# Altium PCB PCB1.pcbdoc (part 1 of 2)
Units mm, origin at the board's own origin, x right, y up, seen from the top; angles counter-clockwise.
Board outline 376.79 x 262.39 mm, 2 copper layers (Top Layer, Bottom Layer), stack 1.58 mm thick; 505 components, 251 nets, 1356 pads, 0 vias.
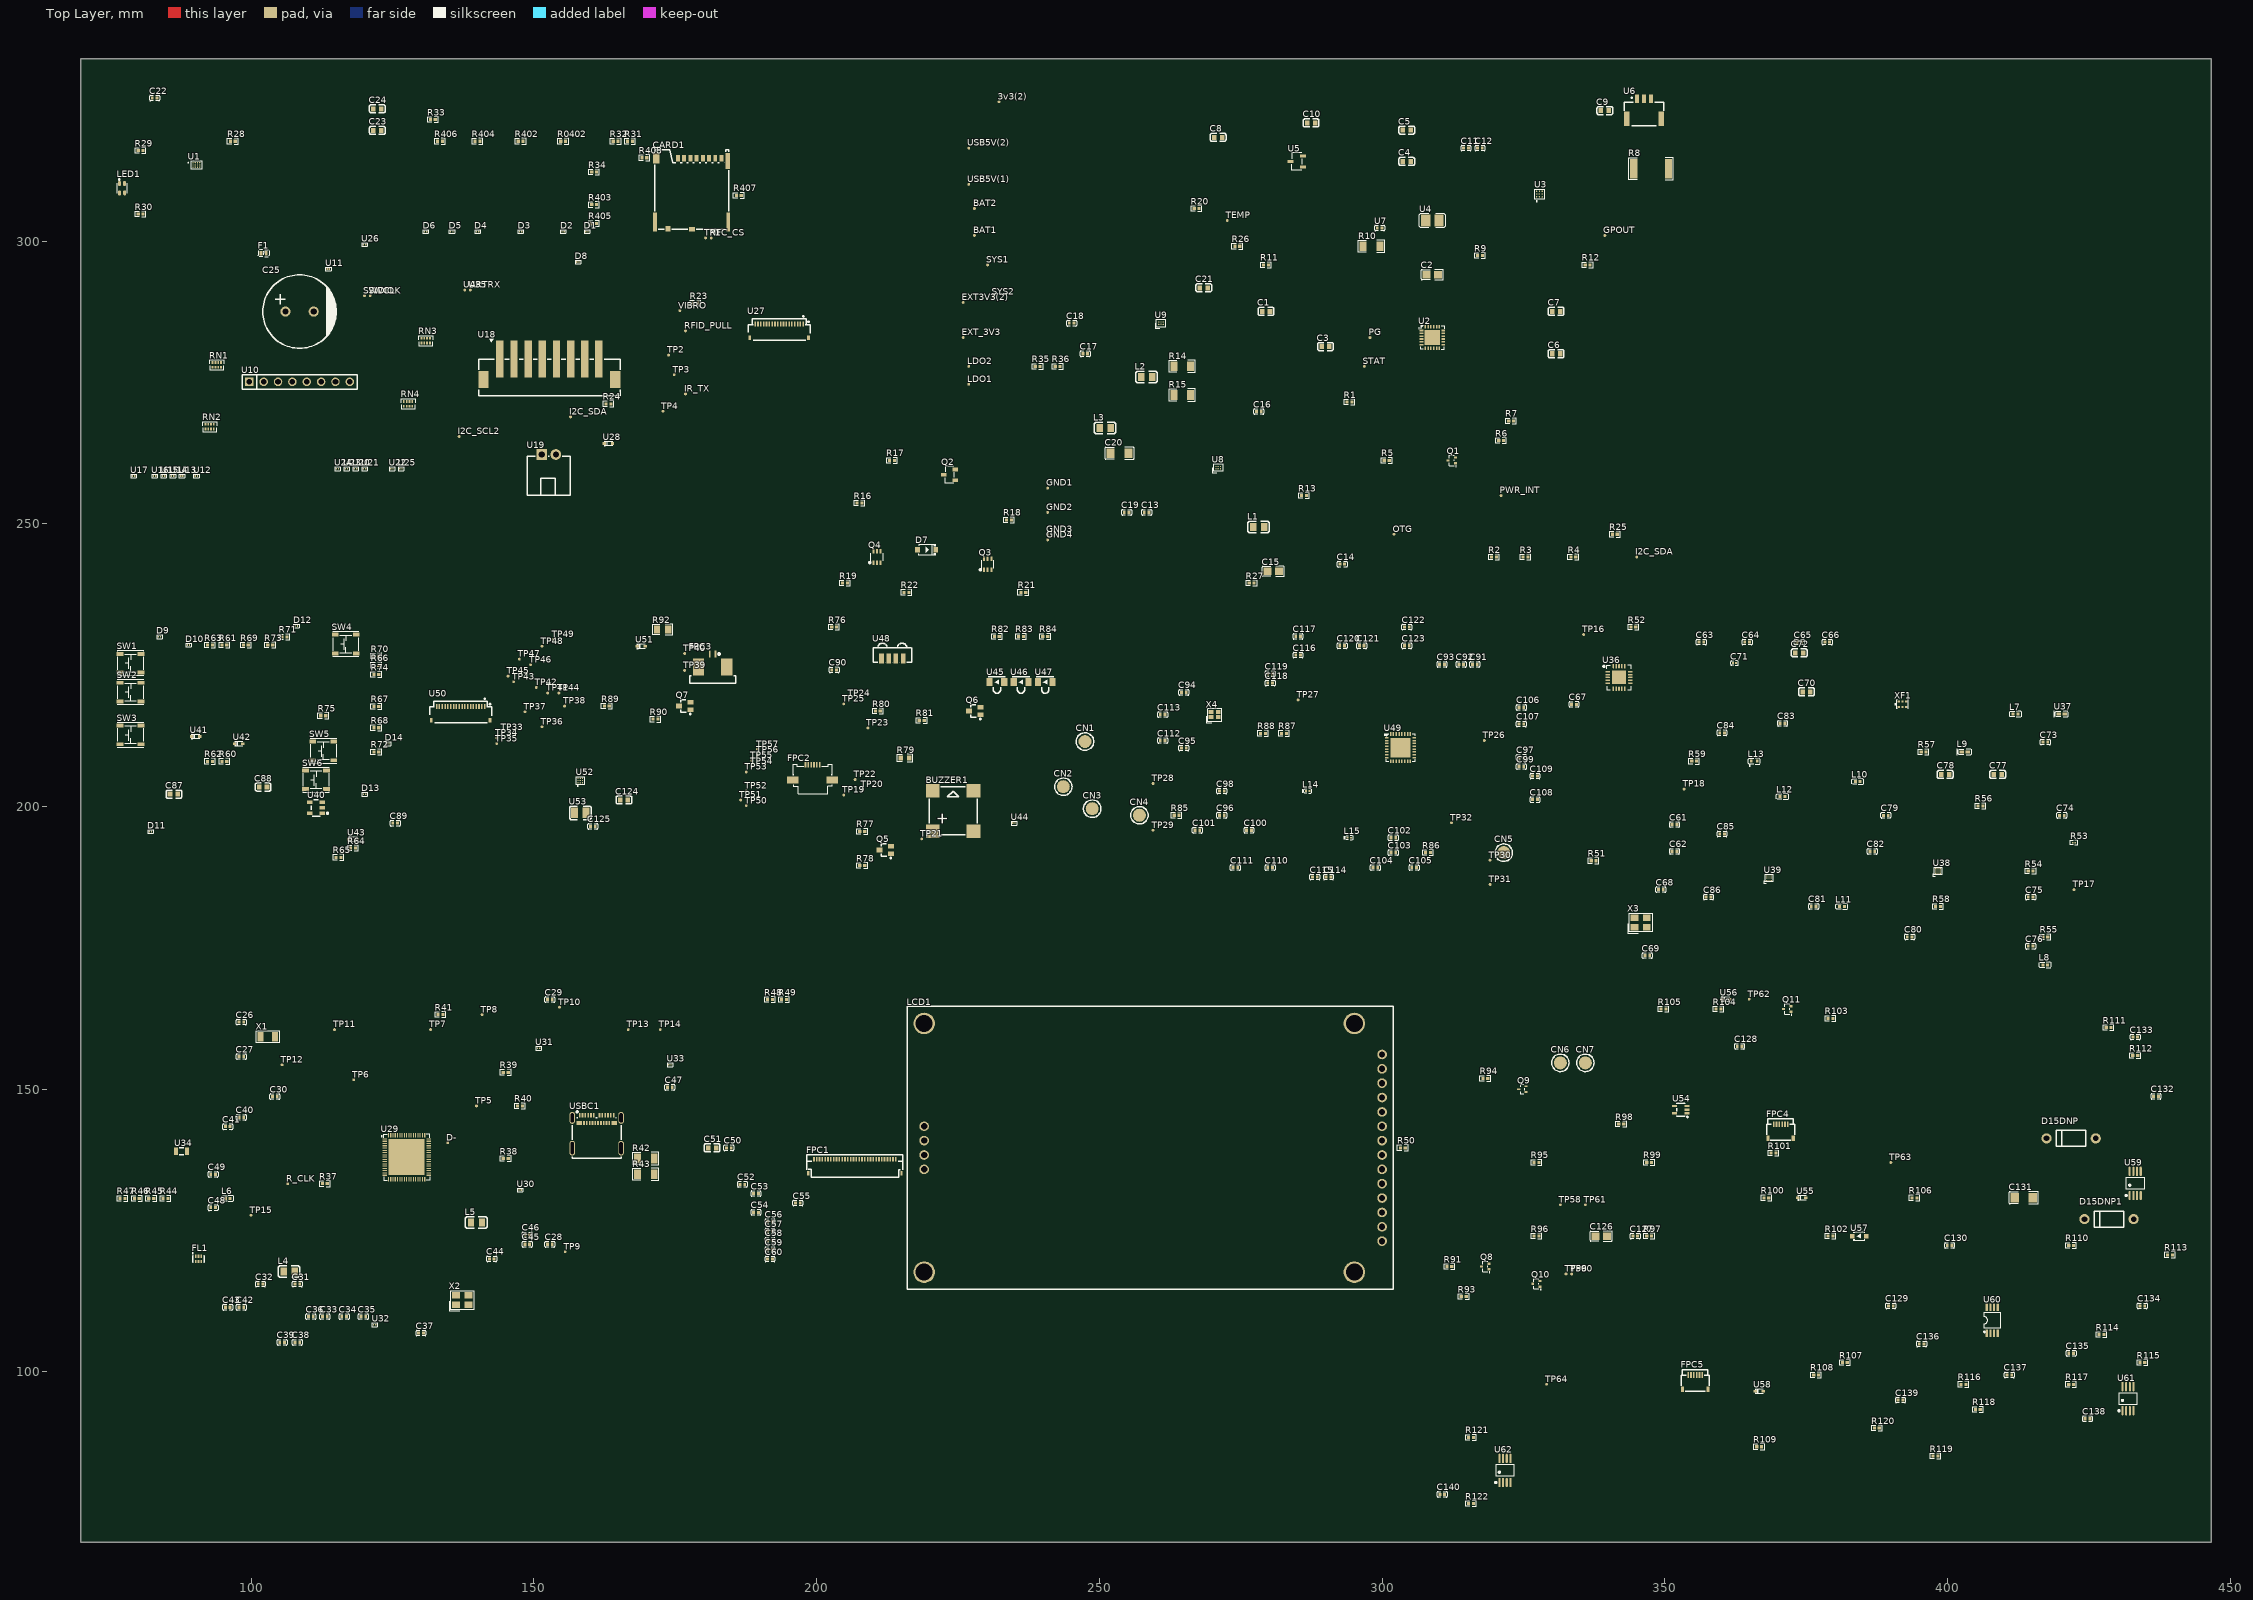
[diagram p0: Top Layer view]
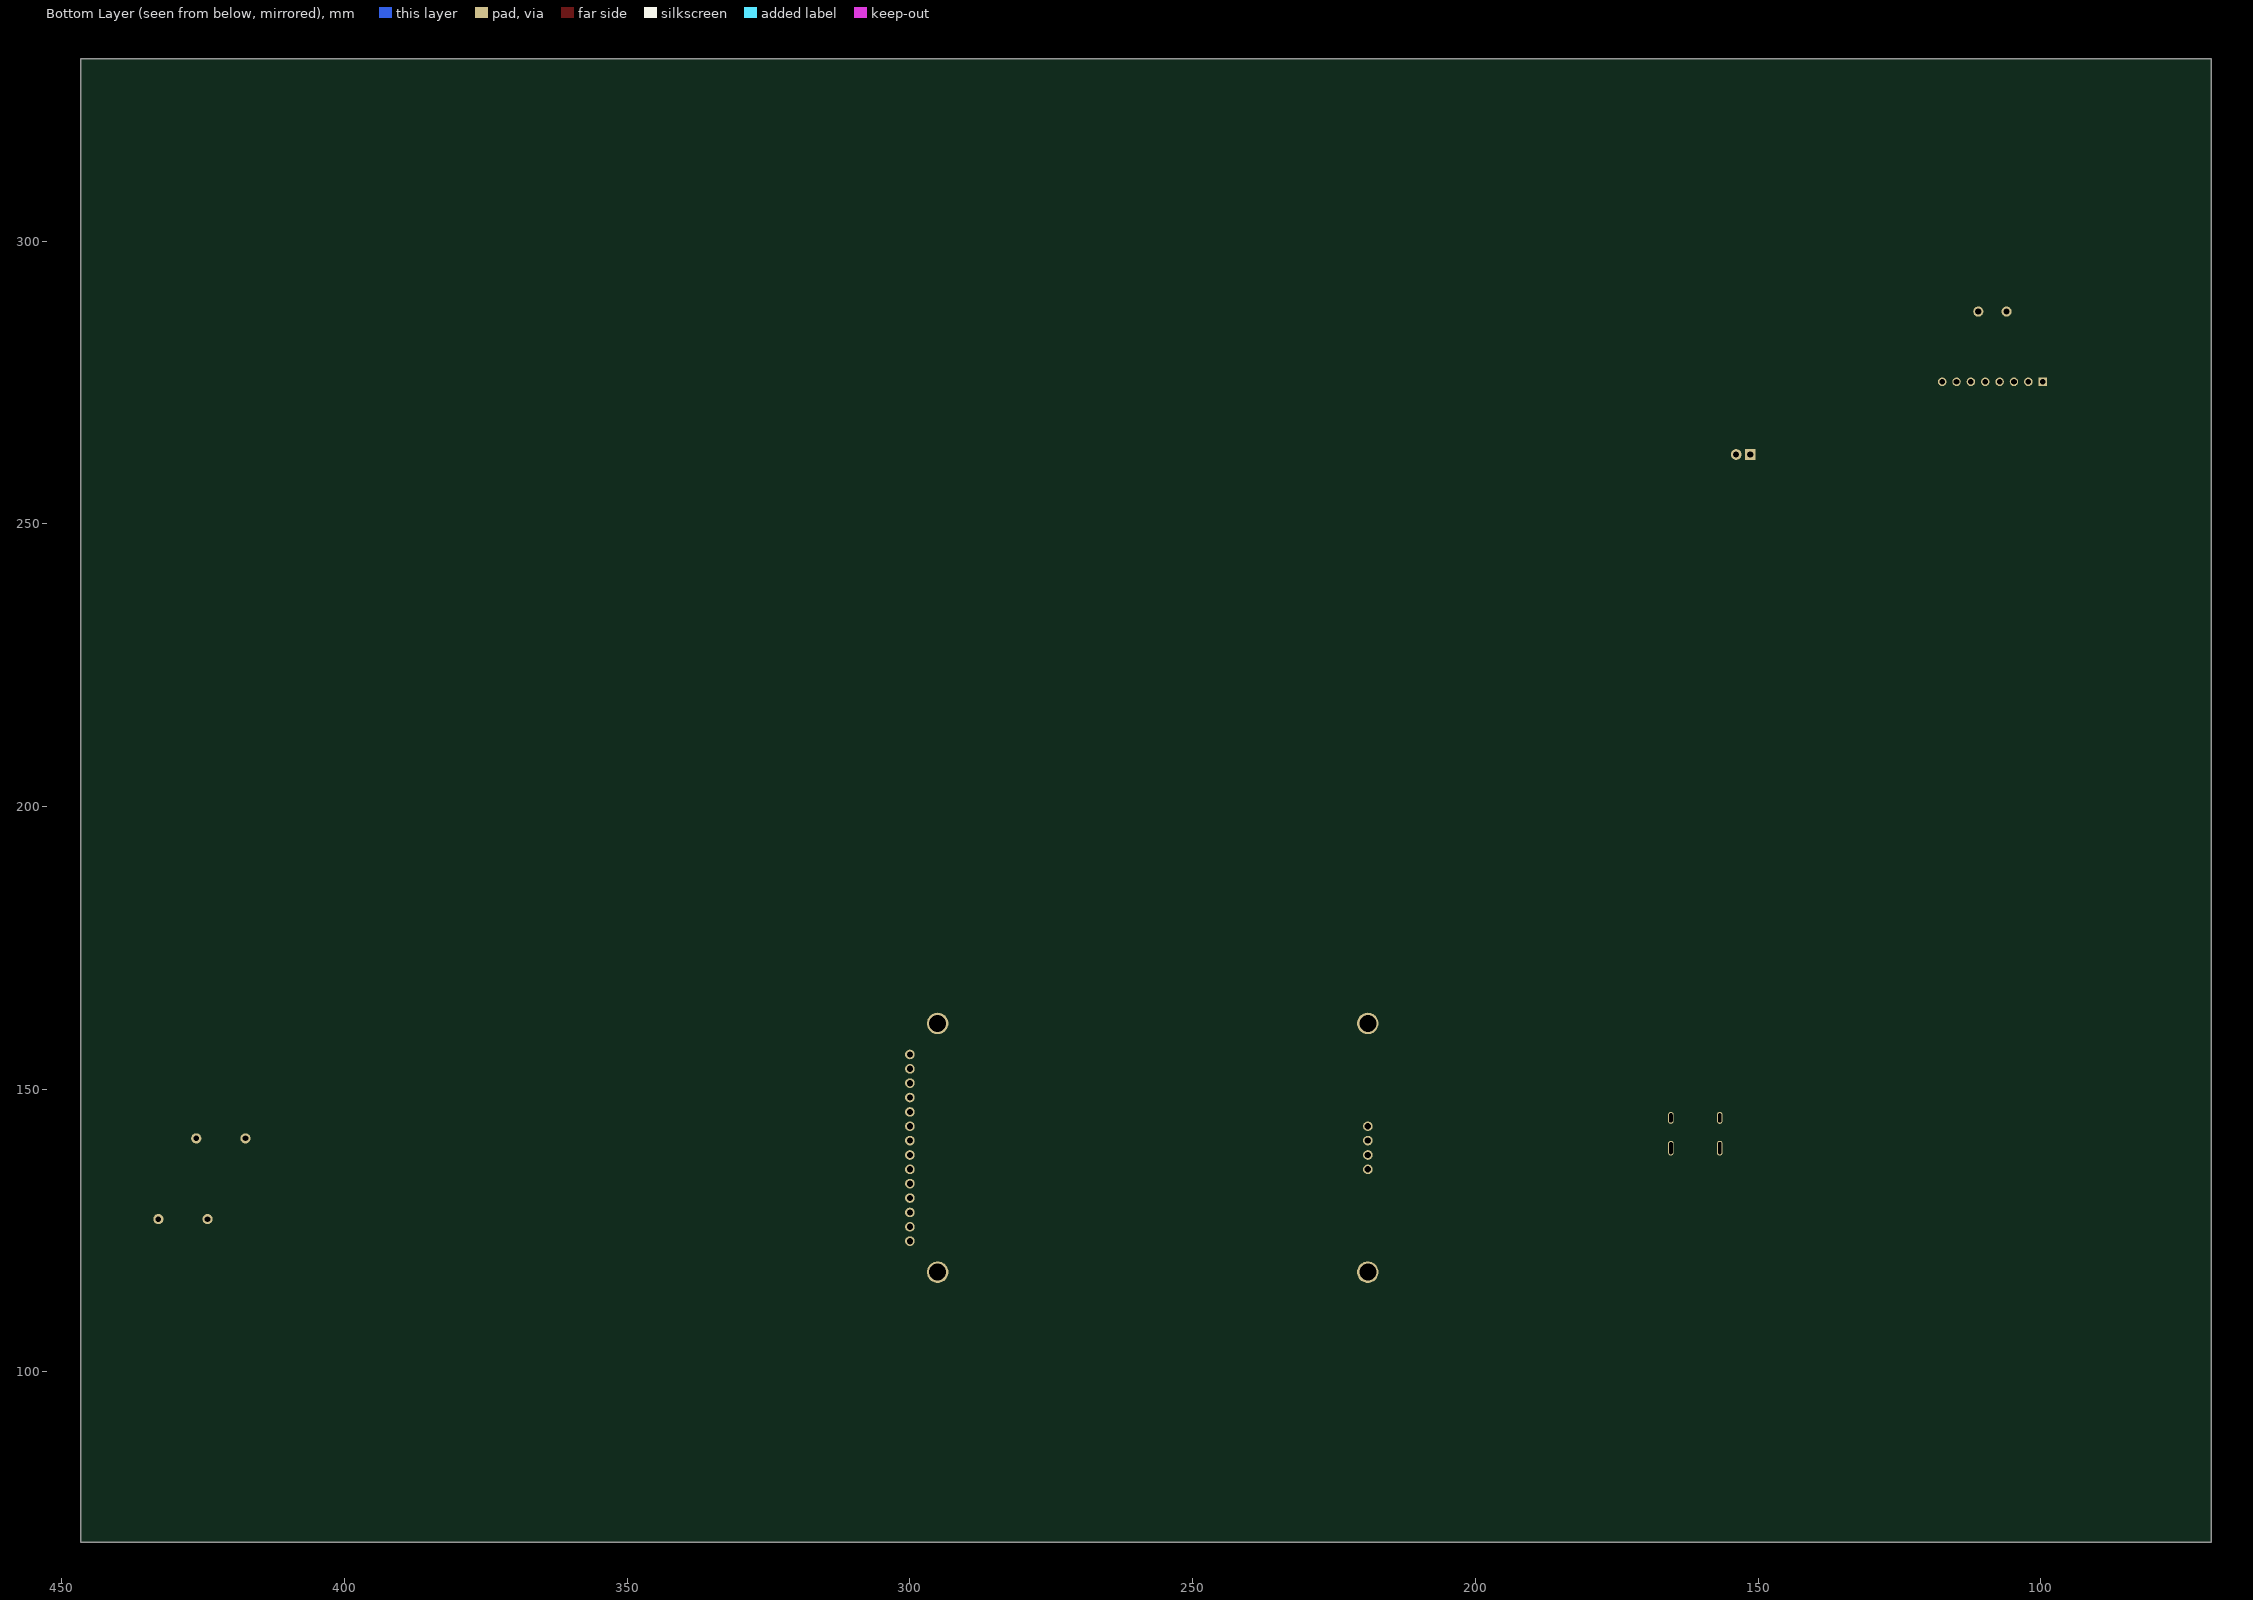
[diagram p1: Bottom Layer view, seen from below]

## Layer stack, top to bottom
Top Solder Mask Layer: solder mask 0.01, Dk 3.3
Top Layer: signal copper 0.035
Dielectric1: surface 1.51, FR4, Dk 4.5
Bottom Layer: signal copper 0.035
Bottom Solder Mask Layer: solder mask 0.01, Dk 3.3

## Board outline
446.638,69.85 69.85,69.85 69.85,332.242 446.638,332.242

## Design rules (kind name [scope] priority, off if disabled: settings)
BoardOutlineClearance copperThickness1oz [All] p0: genericclearance=0.254 ignorepadtopadclearanceinfootprint=FALSE except(0: Arc-SplitContinuation Track-SplitContinuation SMDPad-SplitContinuation THPad-SplitContinuation Via-SplitContinuation Fill-SplitContinuation Poly-SplitContinuation Region-SplitContinuation Text-SplitContinuation)
BoardOutlineClearance copperThickness2oz [All] p0: genericclearance=0.254 ignorepadtopadclearanceinfootprint=FALSE except(0: Arc-SplitContinuation Track-SplitContinuation SMDPad-SplitContinuation THPad-SplitContinuation Via-SplitContinuation Fill-SplitContinuation Poly-SplitContinuation Region-SplitContinuation Text-SplitContinuation)
BoardOutlineClearance otherClearance [All] p0: genericclearance=0.254 ignorepadtopadclearanceinfootprint=FALSE except(0: Arc-SplitContinuation Track-SplitContinuation SMDPad-SplitContinuation THPad-SplitContinuation Via-SplitContinuation Fill-SplitContinuation Poly-SplitContinuation Region-SplitContinuation Text-SplitContinuation)
Clearance copperThickness1oz [All] p1: gap=0.178 ignorepadtopadclearanceinfootprint=FALSE
Clearance copperThickness2oz [All] p1: gap=0.178 ignorepadtopadclearanceinfootprint=FALSE
Clearance otherClearance [All] p1: gap=0.178 ignorepadtopadclearanceinfootprint=FALSE
DiffPairsRouting differentialPair [All] p1: maxuncoupledlength=10 minlimit=6 maxlimit=Infinity mostfreqgap=6 toplayer_minwidth=5 toplayer_prefwidth=10 toplayer_maxwidth=100 bottomlayer_minwidth=5 bottomlayer_prefwidth=10 bottomlayer_maxwidth=100
PasteMaskExpansion pasteMaskExpansion [All] p1: expansion=0
PlaneConnect innerPlane [All] p1: planeconnectstyle=Relief reliefexpansion=0.508 reliefentries=4 reliefconductorwidth=0.254 reliefairgap=0.254
PolygonConnect copperRegion [All] p1: connectstyle=Relief reliefentries=4 reliefconductorwidth=10 polygonreliefangle="90 Angle" airgapwidth=10
RoutingVias viaSize [All] p1: viastyle="Through Hole" holewidth=12.0078 minholewidth=11.811 maxholewidth=248.0314 width=12.0078 minwidth=11.811 maxwidth=248.0314
SolderMaskExpansion solderMaskExpansion [IsVia] p1: useseparateexpansions=TRUE expansion=-1000 expansionbottom=-1000
SolderMaskExpansion solderMaskExpansion [All] p2: useseparateexpansions=TRUE expansion=2 expansionbottom=2
Width copperThickness1oz [All] p1: maxlimit=100 minlimit=5 preferedwidth=10
Width copperThickness2oz [All] p1: maxlimit=100 minlimit=8 preferedwidth=10

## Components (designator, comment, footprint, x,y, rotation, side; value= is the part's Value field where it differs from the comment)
3v3(2) "" Test-Point-0.5mm 232.234,324.662 r0 top
BAT1 "" Test-Point-0.5mm 227.906,300.996 r0 top
BAT2 "" Test-Point-0.5mm 227.906,305.769 r0 top
BUZZER1 "2.7kHz" BUZ-SMD_4P-L8.5-W8.5-P8.50-BR 224.132,199.223 r0 top
C1 "1uF" C0603 279.477,287.57 r0 top
C2 "47nF" C0805 308.886,294.061 r0 top
C3 "10uF" C0603 289.987,281.354 r0 top
C4 "10uF" C0603 304.369,314.095 r0 top
C5 "10uF" C0603 304.369,319.631 r0 top
C6 "10uF" C0603 330.784,280.084 r0 top
C7 "10uF" C0603 330.784,287.57 r0 top
C8 "1uF" C0603 271.003,318.361 r0 top
C9 "1uF" C0603 339.4,323.075 r0 top
C10 "1uF" C0603 287.447,320.901 r0 top
C11 "470nF" C0402#1 314.84,316.448 r0 top
C12 "2.2uF" C0402#1 317.31,316.448 r0 top
C13 "2.2uF" C0402#1 258.352,252.019 r0 top
C14 "10uF" C0402#1 292.954,242.859 r0 top
C15 "4.7uF" C0805 280.747,241.589 r0 top
C16 "2.2uF" C0402#1 278.207,269.864 r0 top
C17 "2.2uF" C0402#1 247.497,280.084 r0 top
C18 "10uF" C0402#1 245.097,285.481 r0 top
C19 "10uF" C0402#1 254.829,252.019 r0 top
C20 "4.7uF" C1206 253.559,262.482 r0 top
C21 "2.2uF" C0603 268.463,291.744 r0 top
C22 "1uF" C0402#1 82.896,325.316 r0 top
C23 "10uF" C0603 122.292,319.579 r0 top
C24 "10uF" C0603 122.292,323.403 r0 top
C25 "DNP tatalum" CAP-TH_BD13.0-P5.00-D0.6-FD 108.536,287.541 r0 top
C26 "18pF" C0402#1 98.238,161.864 r0 top
C27 "18pF" C0402#1 98.238,155.776 r0 top
C28 "DNP" C0402#2 152.813,122.575 r0 top
C29 "DNP" C0402#2 152.813,165.841 r0 top
C30 "100nF" C0402#2 104.178,148.692 r0 top
C31 "0.8pf" C0402#2 108.148,115.542 r0 top
C32 "0.3PF" C0402#2 101.638,115.542 r0 top
C33 "100nF" C0402#2 113.018,109.789 r0 top
C34 "100nF" C0402#2 116.418,109.789 r0 top
C35 "100nF" C0402#2 119.818,109.789 r0 top
C36 "4.7uF" C0402#2 110.548,109.789 r0 top
C37 "100nF" C0402#2 130.01,106.876 r0 top
C38 "1nF" C0402#2 108.148,105.224 r0 top
C39 "10nF" C0402#2 105.448,105.224 r0 top
C40 "1nF" C0402#2 98.238,145.022 r0 top
C41 "100nF" C0402#2 95.838,143.37 r0 top
C42 "100nF" C0402#2 98.238,111.441 r0 top
C43 "100pF" C0402#2 95.838,111.441 r0 top
C44 "4.7uF" C0402#2 142.53,119.979 r0 top
C45 "4.7uF" C0402#2 148.812,122.575 r0 top
C46 "100nF" C0402#2 148.812,124.227 r0 top
C47 "100nF" C0402#2 174.036,150.344 r0 top
C48 "1.5pF" C0402#2 93.242,129.042 r0 top
C49 "100nF" C0402#2 93.242,134.939 r0 top
C50 "100nF" C0402#2 184.47,139.638 r0 top
C51 "10uF" C0603 181.503,139.638 r0 top
C52 "DNP" C0402#2 186.87,133.183 r0 top
C53 "DNP" C0402#2 189.27,131.531 r0 top
C54 "2.2uF" C0402#2 189.27,128.228 r0 top
C55 "DNP" C0402#2 196.681,129.88 r0 top
C56 "DNP" C0402#2 191.74,126.576 r0 top
C57 "DNP" C0402#2 191.74,124.925 r0 top
C58 "DNP" C0402#2 191.74,123.273 r0 top
C59 "DNP" C0402#2 191.74,121.621 r0 top
C60 "2.2uF" C0402#2 191.74,119.969 r0 top
C61 "100nF" C0402#2 351.716,196.799 r0 top
C62 "100nF" C0402#2 351.716,192.062 r0 top
C63 "100nF" C0402#2 356.457,229.085 r0 top
C64 "100nF" C0402#2 364.553,229.085 r0 top
C65 "100nF" C0402#2 373.792,229.085 r0 top
C66 "100nF" C0402#2 378.732,229.085 r0 top
C67 "100nF" C0402#2 333.94,218.076 r0 top
C68 "9pF" C0402#2 349.316,185.302 r0 top
C69 "9pF" C0402#2 346.916,173.643 r0 top
C70 "100pF" C0603 375.062,220.288 r0 top
C71 "0.6pF" C0201 362.34,225.368 r0 top
C72 "100pF" C0603 373.792,227.172 r0 top
C73 "DNP" C0402#2 417.307,211.39 r0 top
C74 "1.2pF" C0402#2 420.229,198.451 r0 top
C75 "DNP" C0402#2 414.711,183.976 r0 top
C76 "DNP" C0402#2 414.711,175.295 r0 top
C77 "10pF" C0603 408.883,205.681 r0 top
C78 "10pF" C0603 399.591,205.681 r0 top
C79 "22pF" C0402#2 389.115,198.451 r0 top
C80 "8.2pF" C0402#2 393.31,176.946 r0 top
C81 "DNP" C0402#2 376.332,182.325 r0 top
C82 "10nF" C0402#2 386.715,192.062 r0 top
C83 "DNP" C0402#2 370.825,214.694 r0 top
C84 "DNP" C0402#2 360.127,213.042 r0 top
C85 "100nF" C0402#2 360.127,195.147 r0 top
C86 "10nF" C0402#2 357.727,183.976 r0 top
C87 "10uF" C0603 86.32,202.18 r0 top
C88 "10uF" C0603 102.079,203.45 r0 top
C89 "100nF" C0402#2 125.453,197.049 r0 top
C90 "100nF" C0402#2 203.085,224.178 r0 top
C91 "DNP" C0402#2 316.396,225.128 r0 top
C92 "DNP" C0402#2 313.996,225.128 r0 top
C93 "DNP" C0402#2 310.596,225.128 r0 top
C94 "6pF" C0402#2 264.936,220.173 r0 top
C95 "6pF" C0402#2 264.936,210.353 r0 top
C96 "100pF" C0402#2 271.655,198.456 r0 top
C97 "10pF" C0402#2 324.64,208.701 r0 top
C98 "DNP" C0402#2 271.655,202.746 r0 top
C99 "100pF" C0402#2 324.64,207.049 r0 top
C100 "680pF" C0402#2 276.455,195.805 r0 top
C101 "62pF" C0402#2 267.336,195.805 r0 top
C102 "100pF" C0402#2 301.985,194.479 r0 top
C103 "DNP" C0402#2 301.985,191.84 r0 top
C104 "680pF" C0402#2 298.805,189.189 r0 top
C105 "62pF" C0402#2 305.655,189.189 r0 top
C106 "10pF" C0402#2 324.64,217.521 r0 top
C107 "100pF" C0402#2 324.64,214.599 r0 top
C108 "1uF" C0402#2 327.04,201.203 r0 top
C109 "10nF" C0402#2 327.04,205.398 r0 top
C110 "10nF" C0402#2 280.196,189.189 r0 top
C111 "2.2uF" C0402#2 274.055,189.189 r0 top
C112 "10nF" C0402#2 261.196,211.679 r0 top
C113 "2.2uF" C0402#2 261.196,216.251 r0 top
C114 "10nF" C0402#2 290.522,187.538 r0 top
C115 "2.2uF" C0402#2 288.122,187.538 r0 top
C116 "10nF" C0402#2 285.137,226.779 r0 top
C117 "2.2uF" C0402#2 285.137,230.083 r0 top
C118 "10nF" C0402#2 280.196,221.824 r0 top
C119 "2.2uF" C0402#2 280.196,223.476 r0 top
C120 "10nF" C0402#2 292.922,228.431 r0 top
C121 "2.2uF" C0402#2 296.405,228.431 r0 top
C122 "10nF" C0402#2 304.385,231.734 r0 top
C123 "2.2uF" C0402#2 304.385,228.431 r0 top
C124 "22uF" C0603 165.917,201.155 r0 top
C125 "10uF" C0402#2 160.409,196.483 r0 top
C126 "3.3nF" C0805 338.739,124.016 r0 top
C127 "DNP" C0402#2 344.77,124.016 r0 top
C128 "100nF" C0402#2 363.225,157.585 r0 top
C129 "10nF" C0402#2 389.985,111.679 r0 top
C130 "1nF" C0402#2 400.367,122.366 r0 top
C131 "220nF" C1206 413.483,130.798 r0 top
C132 "100nF" C0402#2 436.873,148.735 r0 top
C133 "dnp" C0402#2 433.203,159.237 r0 top
C134 "4.7nF" C0402#2 434.473,111.679 r0 top
C135 "100pF" C0402#2 421.873,103.297 r0 top
C136 "100nF" C0402#2 395.426,104.948 r0 top
C137 "4.7nF" C0402#2 410.943,99.462 r0 top
C138 "100pF" C0402#2 424.763,91.715 r0 top
C139 "100pF" C0402#2 391.685,95.016 r0 top
C140 "1uF" C0402#2 310.635,78.349 r0 top
CARD1 "5033981892" TF-SMD_503398-1892 177.877,308.398 r0 top
CN1 "YTC1P-3515-M20" CONN-SMD_YTC1P-3515-M20 247.46,211.491 r0 top
CN2 "YTC1P-3515-M20" CONN-SMD_YTC1P-3515-M20 243.615,203.503 r0 top
CN3 "YTC1P-3515-M20" CONN-SMD_YTC1P-3515-M20 248.73,199.61 r0 top
CN4 "YTC1P-3515-M20" CONN-SMD_YTC1P-3515-M20 257.074,198.456 r0 top
CN5 "YTC1P-3515-M20" CONN-SMD_YTC1P-3515-M20 321.518,191.84 r0 top
CN6 "YTC1P-3515-M20" CONN-SMD_YTC1P-3515-M20 331.527,154.664 r0 top
CN7 "YTC1P-3515-M20" CONN-SMD_YTC1P-3515-M20 335.949,154.664 r0 top
D1 "ESD241B1W0201E6327XTSA1" WLL-2-3_L0.6-W0.3-P0.36-BI 159.364,301.684 r0 top
D2 "ESD241B1W0201E6327XTSA1" WLL-2-3_L0.6-W0.3-P0.36-BI 155.161,301.684 r0 top
D3 "ESD241B1W0201E6327XTSA1" WLL-2-3_L0.6-W0.3-P0.36-BI 147.643,301.684 r0 top
D4 "ESD241B1W0201E6327XTSA1" WLL-2-3_L0.6-W0.3-P0.36-BI 140.023,301.684 r0 top
D5 "ESD241B1W0201E6327XTSA1" WLL-2-3_L0.6-W0.3-P0.36-BI 135.453,301.684 r0 top
D6 "ESD241B1W0201E6327XTSA1" WLL-2-3_L0.6-W0.3-P0.36-BI 130.841,301.684 r0 top
D7 "DNP" SOD-123_L2.7-W1.6-LS3.7-FD 219.446,245.399 r0 top
D8 "ESD241B1W0201E6327XTSA1" WLL-2-3_L0.6-W0.3-P0.36-BI 157.763,296.311 r0 top
D9 "ESD241B1W0201E6327XTSA1" WLL-2-3_L0.6-W0.3-P0.36-BI 83.753,230.006 r0 top
D10 "ESD241B1W0201E6327XTSA1" WLL-2-3_L0.6-W0.3-P0.36-BI 88.888,228.55 r0 top
D11 "ESD241B1W0201E6327XTSA1" WLL-2-3_L0.6-W0.3-P0.36-BI 82.151,195.592 r0 top
D12 "ESD241B1W0201E6327XTSA1" WLL-2-3_L0.6-W0.3-P0.36-BI 107.961,231.929 r0 top
D13 "ESD241B1W0201E6327XTSA1" WLL-2-3_L0.6-W0.3-P0.36-BI 120.04,202.18 r0 top
D14 "ESD241B1W0201E6327XTSA1" WLL-2-3_L0.6-W0.3-P0.36-BI 124.183,211.105 r0 top
D15DNP "" DO-41_BD2.4-L4.7-P8.70-D0.9-RD 421.873,141.302 r0 top
D15DNP1 "" DO-41_BD2.4-L4.7-P8.70-D0.9-RD 428.573,127.023 r0 top
D- "" Test-Point-0.5mm 134.75,140.532 r0 top
EXT3V3(2) "" Test-Point-0.5mm 225.906,289.157 r0 top
EXT_3V3 "" Test-Point-0.5mm 225.906,282.941 r0 top
F1 "ERBRD2R00X" F0402 102.186,297.867 r0 top
FL1 "LFL182G45TC1A108" FILTET-SMD_0603-6P-L1.6-W0.8-P0.50_LFL182G45TC1A108 90.665,119.979 r0 top
FPC1 "FH34SRJ-30S-0.5SH(50)" FFC-SMD_30P-P0.50_FH34SRJ-30S-0.5SH 206.758,136.386 r0 top
FPC2 "5051100697" FPC-SMD_6P-P0.50_5051100697 199.275,206.043 r0 top
FPC3 "1.0K-LS-2PWB-TW" FPC-SMD_1.0K-LS-2PWB-TW 181.588,225.801 r0 top
FPC4 "FH34SRJ-6S-0.5SH(50)" FFC-SMD_6P-P0.50_FH34SRJ-6S-0.5SH 370.505,142.572 r0 top
FPC5 "FH34SRJ-6S-0.5SH(50)" FFC-SMD_6P-P0.50_FH34SRJ-6S-0.5SH 355.392,98.192 r0 top
GND1 "" Test-Point-0.5mm 240.856,256.319 r0 top
GND2 "" Test-Point-0.5mm 240.856,252.019 r0 top
GND3 "" Test-Point-0.5mm 240.856,248.154 r0 top
GND4 "" Test-Point-0.5mm 240.856,247.154 r0 top
GPOUT "" Test-Point-0.5mm 339.4,300.996 r0 top
I2C_SCL2 "" Test-Point-0.5mm 136.753,265.437 r0 top
I2C_SDA "" Test-Point-0.5mm 345.048,244.129 r0 top
I2C_SDA "" Test-Point-0.5mm 156.462,268.906 r0 top
IR_TX "" Test-Point-0.5mm 176.797,272.966 r0 top
L1 "470nH" L0805 278.207,249.424 r0 top
L2 "470nH" L0805 258.352,275.96 r0 top
L3 "470nH" L0805 251.019,266.943 r0 top
L4 "2.7nh" L0805 106.718,117.761 r0 top
L5 "10uH" L0805 139.83,126.446 r0 top
L6 "3nH" L0402 95.838,130.702 r0 top
L7 "3.3nH" L0402 412.045,216.354 r0 top
L8 "56nH" L0402 417.307,172.001 r0 top
L9 "27nH" L0402-RD 403.08,209.668 r0 top
L10 "22nH" L0402 384.119,204.411 r0 top
L11 "2.7nH" L0402 381.328,182.325 r0 top
L12 "DNP" L0402 370.825,201.76 r0 top
L13 "2.2nH" IND-SMD_L1.0-W0.5_LQG15HN1N6B02D 365.823,208.018 r0 top
L14 "270nH" L0201-RD 286.852,202.746 r0 top
L15 "270nH" L0201-RD 294.192,194.479 r0 top
LCD1 "HS12864G18B" COMM-TH_HS12864G18B 259.51,139.638 r0 top
LDO1 "" Test-Point-0.5mm 226.906,274.69 r0 top
LDO2 "" Test-Point-0.5mm 226.906,277.853 r0 top
LED1 "LTST-C19HE1WT" LED-ARRAY-SMD_4P-L1.6-W1.6-TL-CW 77.152,309.359 r0 top
NFC_CS "" Test-Point-0.5mm 181.338,300.553 r0 top
OTG "" Test-Point-0.5mm 302.102,248.154 r0 top
PG "" Test-Point-0.5mm 297.862,282.941 r0 top
PWR_INT "" Test-Point-0.5mm 321.051,254.994 r0 top
Q1 "DMN313DLT-7" SOT-523-3_L1.6-W0.8-P1.00-LS1.6-BR 312.33,261.212 r0 top
Q2 "DMP1045U-7" SOT-23-3_L2.9-W1.3-P1.90-LS2.4-BR 223.496,258.672 r0 top
Q3 "MMDT2907A-7-F" SOT-363_L2.0-W1.3-P0.65-LS2.1-BL 230.234,242.859 r0 top
Q4 "MMDT2907A-7-F" SOT-363_L2.0-W1.3-P0.65-LS2.1-BL 210.662,244.129 r0 top
Q5 "DMN2058UW-7" SOT-323-3_L2.2-W1.3-P1.30-LS2.1-BR 212.096,192.3 r0 top
Q6 "DMN2058UW-7" SOT-323-3_L2.2-W1.3-P1.30-LS2.1-BR 227.942,216.888 r0 top
Q7 "DMN2058UW-7" SOT-323-3_L2.2-W1.3-P1.30-LS2.1-BR 176.636,217.767 r0 top
Q8 "CJE3134K" SOT-523-3_L1.6-W0.8-P1.00-LS1.6-BR 318.257,118.646 r0 top
Q9 "CJE3139K" SC-75-3_L1.6-W0.8-P1.00-LS1.7-BR 324.813,150.005 r0 top
Q10 "CJE3134K" SOT-523-3_L1.6-W0.8-P1.00-LS1.6-BR 327.296,115.577 r0 top
Q11 "DMN5L06TK-7" SOT-523-3_L1.6-W0.8-P1.00-LS1.6-BR 371.661,164.187 r0 top
R1 "470Ω" R0402 294.224,271.514 r0 top
R2 "4.7kΩ" R0402 319.781,244.129 r0 top
R3 "1.5kΩ" R0402 325.362,244.129 r0 top
R4 "1.5kΩ" R0402 333.822,244.129 r0 top
R5 "10K" R0402 300.832,261.212 r0 top
R6 "100Ω" R0402 321.051,264.725 r0 top
R7 "10K" R0402 322.821,268.213 r0 top
R8 "10mΩ" R2512 347.588,312.825 r0 top
R9 "10K" R0402 317.31,297.441 r0 top
R10 "5.23ohm" R1206 298.132,299.09 r0 top
R11 "30.1kΩ" R0402 279.477,295.791 r0 top
R12 "10K" R0402 336.363,295.791 r0 top
R13 "10K" R0402 286.177,254.994 r0 top
R14 "1R5" R1206 264.653,277.853 r0 top
R15 "1R5" R1206 264.653,272.784 r0 top
R16 "nettie" R0402 207.564,253.67 r0 top
R17 "nettie" R0402 213.334,261.212 r0 top
R18 "100kΩ" R0402 234.004,250.694 r0 top
R19 "100kΩ" R0402 205.023,239.535 r0 top
R20 "DNP" R0402 267.193,305.769 r0 top
R21 "10K" R0402 236.545,237.885 r0 top
R22 "10K" R0402 215.875,237.885 r0 top
R23 "51Ω" R0402 178.568,289.026 r0 top
R24 "1kΩ" R0402 163.175,271.231 r0 top
R25 "nettie" R0402 341.17,248.154 r0 top
R26 "nettie" R0402 274.396,299.09 r0 top
R27 "nettie" R0402 276.937,239.535 r0 top
R28 "0Ω" R0402 96.729,317.667 r0 top
R29 "0Ω" R0402 80.426,316.018 r0 top
R30 "0Ω" R0402 80.426,304.79 r0 top
R31 "47kΩ" R0402 166.986,317.667 r0 top
R32 "47kΩ" R0402 164.445,317.667 r0 top
R33 "0Ω" R0402 132.111,321.491 r0 top
R34 "51Ω" R0402 160.634,312.208 r0 top
R35 "3.3Ω" R0402 239.086,277.853 r0 top
R36 "3.3Ω" R0402 242.627,277.853 r0 top
R37 "51Ω" R0402 113.018,133.288 r0 top
R38 "22Ω" R0402 145.001,137.75 r0 top
R39 "DNP" R0402 145.001,152.995 r0 top
R40 "22Ω" R0402 147.542,147.042 r0 top
R41 "51Ω" R0402 133.48,163.19 r0 top
R42 "5.1K" R1206 169.796,137.75 r0 top
R43 "5.1K" R1206 169.796,134.939 r0 top
R44 "0Ω" R0402 84.843,130.702 r0 top
R45 "DNP" R0402 82.302,130.702 r0 top
R46 "DNP" R0402 79.761,130.702 r0 top
R47 "DNP" R0402 77.22,130.702 r0 top
R48 "DNP" R0402 191.74,165.842 r0 top
R49 "DNP" R0402 194.211,165.842 r0 top
R50 "0Ω" R0402 303.665,139.638 r0 top
R51 "330Ω" R0402 337.411,190.411 r0 top
R52 "56kΩ" R0402 344.446,231.736 r0 top
R53 "0Ω" R0201 422.377,193.605 r0 top
R54 "0Ω" R0402 414.711,188.598 r0 top
R55 "0Ω" R0402 417.307,176.946 r0 top
R56 "0Ω" R0402 405.845,200.101 r0 top
R57 "0Ω" R0402 395.78,209.668 r0 top
R58 "0Ω" R0402 398.321,182.325 r0 top
R59 "0Ω" R0402 355.187,208.018 r0 top
R60 "100kΩ" R0402 95.235,208 r0 top
R61 "DNP" R0402 95.235,228.55 r0 top
R62 "100kΩ" R0402 92.694,208 r0 top
R63 "10K" R0402 92.694,228.55 r0 top
R64 "510Ω" R0402 117.973,192.666 r0 top
R65 "10K" R0402 115.433,191.016 r0 top
R66 "330Ω" R0402 122.111,224.977 r0 top
R67 "330Ω" R0402 122.111,217.702 r0 top
R68 "330Ω" R0402 122.111,213.935 r0 top
R69 "10K" R0402 99.042,228.55 r0 top
R70 "330Ω" R0402 122.111,226.627 r0 top
R71 "10K" R0402 105.89,230.006 r0 top
R72 "330Ω" R0402 122.111,209.649 r0 top
R73 "10K" R0402 103.349,228.55 r0 top
R74 "330Ω" R0402 122.111,223.328 r0 top
R75 "10K" R0402 112.732,216.052 r0 top
R76 "10Ω" R0402 203.085,231.736 r0 top
R77 "150Ω" R0402 208.055,195.602 r0 top
R78 "10K" R0402 208.055,189.552 r0 top
R79 "22Ω" R0603 215.6,208.583 r0 top
R80 "150Ω" R0402 210.826,216.888 r0 top
R81 "10K" R0402 218.582,215.238 r0 top
R82 "39Ω" R0402 231.872,230.086 r0 top
R83 "39Ω" R0402 236.148,230.086 r0 top
R84 "39Ω" R0402 240.423,230.086 r0 top
R85 "0Ω" R0402 263.666,198.456 r0 top
R86 "0Ω" R0402 308.126,191.84 r0 top
R87 "DNP" R0402 282.666,212.949 r0 top
R88 "DNP" R0402 278.926,212.949 r0 top
R89 "150Ω" R0402 162.879,217.767 r0 top
R90 "10K" R0402 171.486,215.442 r0 top
R91 "51Ω" R0402 311.905,118.646 r0 top
R92 "22Ω" R0805 172.756,231.317 r0 top
R93 "10K" R0402 314.446,113.33 r0 top
R94 "510Ω" R0402 318.257,151.918 r0 top
R95 "4.7Ω" R0402 327.296,137.05 r0 top
R96 "4.7Ω" R0402 327.296,124.016 r0 top
R97 "DNP" R0402 347.24,124.016 r0 top
R98 "330kΩ" R0402 342.299,143.842 r0 top
R99 "DNP" R0402 347.24,137.05 r0 top
R100 "0Ω" R0402 367.965,130.798 r0 top
R101 "10K" R0402 369.235,138.7 r0 top
R102 "330kΩ" R0402 379.314,124.016 r0 top
R103 "330Ω" R0402 379.314,162.537 r0 top
R104 "220Ω" R0402 359.489,164.187 r0 top
R105 "220Ω" R0402 349.781,164.187 r0 top
R106 "5.1kΩ" R0402 394.156,130.798 r0 top
R107 "47kΩ" R0402 381.854,101.646 r0 top
R108 "51Ω" R0402 376.773,99.462 r0 top
R109 "10K" R0402 366.695,86.765 r0 top
R110 "1MΩ" R0402 421.873,122.366 r0 top
R111 "" R0402 428.503,160.887 r0 top
R112 "4.7kΩ" R0402 433.203,155.934 r0 top
R113 "" R0402 439.344,120.716 r0 top
R114 "" R0402 427.233,106.599 r0 top
R115 "10K" R0402 434.473,101.646 r0 top
R116 "1kΩ" R0402 402.837,97.812 r0 top
R117 "1kΩ" R0402 421.873,97.812 r0 top
R118 "10K" R0402 405.378,93.365 r0 top
R119 "33kΩ" R0402 397.896,85.115 r0 top
R120 "20kΩ" R0402 387.515,90.064 r0 top
R121 "33kΩ" R0402 315.716,88.415 r0 top
R122 "33kΩ" R0402 315.716,76.699 r0 top
R0402 "DNP" R0402 155.161,317.667 r0 top
R402 "DNP" R0402 147.643,317.667 r0 top
R403 "51Ω" R0402 160.634,306.439 r0 top
R404 "DNP" R0402 140.023,317.667 r0 top
R405 "51Ω" R0402 160.634,303.14 r0 top
R406 "47kΩ" R0402 133.381,317.667 r0 top
R407 "150Ω" R0402 186.228,308.089 r0 top
R408 "150Ω" R0402 169.527,314.748 r0 top
R_CLK "" Test-Point-0.5mm 106.448,133.288 r0 top
RFID_PULL "" Test-Point-0.5mm 176.797,284.127 r0 top
RN1 "51Ω" RES-ARRAY-SMD_0402-8P-L2.0-W1.0-BL 93.903,278.118 r0 top
RN2 "51Ω" RES-ARRAY-SMD_0402-8P-L2.0-W1.0-BL 92.633,267.172 r0 top
RN3 "51Ω" RES-ARRAY-SMD_0402-8P-L2.0-W1.0-BL 130.841,282.393 r0 top
RN4 "51Ω" RES-ARRAY-SMD_0402-8P-L2.0-W1.0-BL 127.732,271.231 r0 top
STAT "" Test-Point-0.5mm 296.862,277.853 r0 top
SW1 "SKRMAAE010" SW-SMD_4P-L4.5-W4.5-P3.30-S3.75 78.65,225.357 r0 top
SW2 "SKRMAAE010" SW-SMD_4P-L4.5-W4.5-P3.30-S3.75 78.65,220.242 r0 top
SW3 "SKRMAAE010" SW-SMD_4P-L4.5-W4.5-P3.30-S3.75 78.65,212.665 r0 top
SW4 "SKRMAAE010" SW-SMD_4P-L4.5-W4.5-P3.30-S3.75 116.703,228.736 r0 top
SW5 "SKRMAAE010" SW-SMD_4P-L4.5-W4.5-P3.30-S3.75 112.732,209.835 r0 top
SW6 "SKRMAAE010" SW-SMD_4P-L4.5-W4.5-P3.30-S3.75 111.462,204.72 r0 top
SWCLK "" Test-Point-0.5mm 121.022,290.351 r0 top
SWDIO "" Test-Point-0.5mm 120.022,290.351 r0 top
SYS1 "" Test-Point-0.5mm 230.234,295.791 r0 top
SYS2 "SYS1" Test-Point-0.5mm 231.234,290.157 r0 top
TEMP "" Test-Point-0.5mm 272.626,303.647 r0 top
TP1 "RFID_IN" Test-Point-0.5mm 180.338,300.553 r0 top
TP2 "RFID_OUT" Test-Point-0.5mm 173.797,279.853 r0 top
TP3 "SPEAKER" Test-Point-0.5mm 174.797,276.383 r0 top
TP4 "RFID_CARRIED" Test-Point-0.5mm 172.797,269.906 r0 top
TP5 "D+" Test-Point-0.5mm 139.83,147.042 r0 top
TP6 "D_MI" Test-Point-0.5mm 118.118,151.67 r0 top
TP7 "R_MI" Test-Point-0.5mm 131.71,160.539 r0 top
TP8 "R_MO" Test-Point-0.5mm 140.83,163.19 r0 top
TP9 "D_MO" Test-Point-0.5mm 155.513,121.249 r0 top
TP10 "D_SCK" Test-Point-0.5mm 154.513,164.515 r0 top
TP11 "BOOT" Test-Point-0.5mm 114.718,160.539 r0 top
TP12 "NRST" Test-Point-0.5mm 105.448,154.319 r0 top
TP13 "VBUS2" Test-Point-0.5mm 166.659,160.539 r0 top
TP14 "VBUS1" Test-Point-0.5mm 172.336,160.539 r0 top
TP15 "BLE" Test-Point-0.5mm 99.938,127.716 r0 top
TP16 "CC_PWD" Test-Point-0.5mm 335.64,230.411 r0 top
TP17 "Balun" Test-Point-0.5mm 422.377,185.302 r0 top
TP18 "SUB1Ghz" Test-Point-0.5mm 353.416,203.077 r0 top
TP19 "SYS" Test-Point-0.5mm 204.785,202.033 r0 top
TP20 "SPEAKER" Test-Point-0.5mm 208.055,203.033 r0 top
TP21 "SPEAKER 1" Test-Point-0.5mm 218.582,194.277 r0 top
TP22 "iBTN" Test-Point-0.5mm 206.785,204.773 r0 top
TP23 "IR_TX" Test-Point-0.5mm 209.055,213.913 r0 top
TP24 "IR_RX" Test-Point-0.5mm 205.785,219.158 r0 top
TP25 "GND" Test-Point-0.5mm 204.785,218.158 r0 top
TP26 "CP1" Test-Point-0.5mm 318.096,211.679 r0 top
TP27 "CP2" Test-Point-0.5mm 285.137,218.847 r0 top
TP28 "AN2" Test-Point-0.5mm 259.496,204.072 r0 top
TP29 "ANT1" Test-Point-0.5mm 259.496,195.805 r0 top
TP30 "AN1" Test-Point-0.5mm 319.096,190.515 r0 top
TP31 "ANT2" Test-Point-0.5mm 319.096,186.212 r0 top
TP32 "CP3" Test-Point-0.5mm 312.296,197.131 r0 top
TP33 "NFC_CS" Test-Point-0.5mm 144.407,213.118 r0 top
TP34 "GND2" Test-Point-0.5mm 143.407,212.118 r0 top
TP35 "GND3" Test-Point-0.5mm 143.407,211.118 r0 top
TP36 "SPI_R_SCK" Test-Point-0.5mm 151.407,214.118 r0 top
TP37 "SPI_R_MISO" Test-Point-0.5mm 148.407,216.767 r0 top
TP38 "VIBRO" Test-Point-0.5mm 155.407,217.767 r0 top
TP39 "VIBRO2" Test-Point-0.5mm 176.636,224.071 r0 top
TP40 "VIBRO3" Test-Point-0.5mm 176.636,227.071 r0 top
TP41 "RFID_PULL" Test-Point-0.5mm 152.407,220.071 r0 top
TP42 "RFID_OUT" Test-Point-0.5mm 150.407,221.071 r0 top
TP43 "SPI_R_MOSI" Test-Point-0.5mm 146.407,222.071 r0 top
TP44 "" Test-Point-0.5mm 154.407,220.071 r0 top
TP45 "iBTN" Test-Point-0.5mm 145.407,223.071 r0 top
TP46 "SPEAKER" Test-Point-0.5mm 149.407,225.071 r0 top
TP47 "IR_TX" Test-Point-0.5mm 147.407,226.071 r0 top
TP48 "IR_RX" Test-Point-0.5mm 151.407,228.339 r0 top
TP49 "RFID_CARRIED" Test-Point-0.5mm 153.407,229.574 r0 top
TP50 "GND_2" Test-Point-0.5mm 187.54,200.155 r0 top
TP51 "GND_1" Test-Point-0.5mm 186.54,201.155 r0 top
TP52 "3V3_2" Test-Point-0.5mm 187.54,202.743 r0 top
TP53 "3V3_1" Test-Point-0.5mm 187.54,206.118 r0 top
TP54 "5V_2" Test-Point-0.5mm 188.54,207.118 r0 top
TP55 "5V_1" Test-Point-0.5mm 188.54,208.118 r0 top
TP56 "SYS2" Test-Point-0.5mm 189.54,209.118 r0 top
TP57 "SYS1" Test-Point-0.5mm 189.54,210.118 r0 top
TP58 "AR1" Test-Point-0.5mm 331.527,129.563 r0 top
TP59 "ANT3" Test-Point-0.5mm 332.527,117.322 r0 top
TP60 "ANT4" Test-Point-0.5mm 333.527,117.322 r0 top
TP61 "AR2" Test-Point-0.5mm 335.949,129.563 r0 top
TP62 "NFC_IRQ" Test-Point-0.5mm 364.925,165.932 r0 top
TP63 "DET" Test-Point-0.5mm 389.985,137.05 r0 top
TP64 "1.65V" Test-Point-0.5mm 329.105,97.812 r0 top
U1 "LP5562TMX/NOPB" DSBGA-12_L1.7-W1.3-R3-C4-P0.40-TL 90.278,313.478 r0 top
U2 "BQ25896RTWR" QFN-24_L4.0-W4.0-P0.50-TL-EP2.7 308.886,282.941 r0 top
U3 "BQ27220YZFR" DSBGA-9_L1.7-W1.6-R3-C3-P0.50-BL 327.825,308.33 r0 top
U4 "1uH" L1008 308.886,303.647 r0 top
U5 "XC6206P332MR" SOT-23-3_L3.0-W1.7-P0.95-LS2.9-BR 284.907,314.095 r0 top
U6 "1.25-3PWTDK" CONN-SMD_3P-P1.25_SHOU_1.25-3PWTDK 346.318,323.392 r0 top
U7 "4.7uF" C0402#1 299.562,302.321 r0 top
U8 "LM3281YFQR" DSBGA-6_L1.4-W1.1-R3-C2-P0.40-BL 271.003,259.942 r0 top
U9 "LM3281YFQR" DSBGA-6_L1.4-W1.1-R3-C2-P0.40-BL 260.894,285.481 r0 top
U10 "2.54-1*8" HDR-TH_8P-P2.54-V-M 108.536,275.113 r0 top
U11 "ESD230B1W0201E6327XTSA1" WLL-2-1_L0.6-W0.3-BI 113.616,295.049 r0 top
U12 "ESD230B1W0201E6327XTSA1" WLL-2-1_L0.6-W0.3-BI 90.278,258.465 r0 top
U13 "ESD230B1W0201E6327XTSA1" WLL-2-1_L0.6-W0.3-BI 87.701,258.465 r0 top
U14 "ESD230B1W0201E6327XTSA1" WLL-2-1_L0.6-W0.3-BI 86.099,258.465 r0 top
U15 "ESD230B1W0201E6327XTSA1" WLL-2-1_L0.6-W0.3-BI 84.498,258.465 r0 top
U16 "ESD230B1W0201E6327XTSA1" WLL-2-1_L0.6-W0.3-BI 82.896,258.465 r0 top
U17 "ESD230B1W0201E6327XTSA1" WLL-2-1_L0.6-W0.3-BI 79.156,258.465 r0 top
U18 "2.54mm-8P LT" CONN-SMD_8P-P2.50_SHOUHAN_2.54MM-8PLT 152.723,277.313 r0 top
U19 "2.54mm-2P WZ" CONN-TH_2P-P2.50_HX-2.54MM-2P-WZ-1 152.621,262.267 r0 top
U20 "ESD230B1W0201E6327XTSA1" WLL-2-1_L0.6-W0.3-BI 118.421,259.727 r0 top
U21 "ESD230B1W0201E6327XTSA1" WLL-2-1_L0.6-W0.3-BI 120.022,259.727 r0 top
U22 "ESD230B1W0201E6327XTSA1" WLL-2-1_L0.6-W0.3-BI 124.86,259.727 r0 top
U23 "ESD230B1W0201E6327XTSA1" WLL-2-1_L0.6-W0.3-BI 116.819,259.727 r0 top
U24 "ESD230B1W0201E6327XTSA1" WLL-2-1_L0.6-W0.3-BI 115.218,259.727 r0 top
U25 "ESD230B1W0201E6327XTSA1" WLL-2-1_L0.6-W0.3-BI 126.462,259.727 r0 top
U26 "ESD230B1W0201E6327XTSA1" WLL-2-1_L0.6-W0.3-BI 120.022,299.423 r0 top
U27 "FH34SRJ-18S-0.5SH(50)" FFC-SMD_18P-P0.50_FH34SRJ-18S-0.5SH 193.375,284.127 r0 top
U28 "1N4148X-TP" SOD-523F_L1.2-W0.8-LS1.7-RD 163.175,264.202 r0 top
U29 "STM32WB55RGV6TR" QFN-68_L8.0-W8.0-P0.40-TL-EP6.4 127.47,137.992 r0 top
U30 "ESD230B1W0201E6327XTSA1" WLL-2-1_L0.6-W0.3-BI 147.542,132.158 r0 top
U31 "ESD230B1W0201E6327XTSA1" WLL-2-1_L0.6-W0.3-BI 150.813,157.233 r0 top
U32 "ESD230B1W0201E6327XTSA1" WLL-2-1_L0.6-W0.3-BI 121.819,108.333 r0 top
U33 "ESD230B1W0201E6327XTSA1" WLL-2-1_L0.6-W0.3-BI 174.036,154.319 r0 top
U34 "1001312" ANT-SMD_L2.0-W1.2-BI 87.664,139.02 r0 top
U35 "UART_TX" Test-Point-0.5mm 138.753,291.351 r0 top
U36 "CC1101RGPR" QFN-20_L4.0-W4.0-P0.5-TL-EP 341.906,222.828 r0 top
U37 "6.8nH" L0402-RD 420.229,216.354 r0 top
U38 "BGS13S4N9E6327XTSA1" TSNP-9_L1.1-W1.1-P0.40-BL 398.321,188.598 r0 top
U39 "BGS13S4N9E6327XTSA1" TSNP-9_L1.1-W1.1-P0.40-BL 368.441,187.328 r0 top
U40 "NC7SZ32M5X" SOT-23-5_L2.9-W1.6-P0.95-LS2.8-BR 111.462,199.775 r0 top
U41 "1N4148X-TP" SOD-523F_L1.2-W0.8-LS1.7-RD 90.158,212.375 r0 top
U42 "1N4148X-TP" SOD-523F_L1.2-W0.8-LS1.7-RD 97.772,211.105 r0 top
U43 "1N4148X-TP" SOD-523F_L1.2-W0.8-LS1.7-RD 117.973,194.226 r0 top
U44 "ESD230B1W0201E6327XTSA1" WLL-2-1_L0.6-W0.3-BI 234.878,197.058 r0 top
U45 "VSMY14940" LED-SMD_VSMY14940 231.872,222.005 r0 top
U46 "VSMY14940" LED-SMD_VSMY14940 236.148,222.005 r0 top
U47 "VSMY14940" LED-SMD_VSMY14940 240.423,222.005 r0 top
U48 "TSOP75338TR" SENSOR-SMD_TSOP75238TR 213.366,226.154 r0 top
U49 "27.12MHz" VFQFPN-32_L5.0-W5.0-P0.50-TL-EP3.5 303.255,210.409 r0 top
U50 "FH34SRJ-18S-0.5SH(50)" FFC-SMD_18P-P0.50_FH34SRJ-18S-0.5SH 137.03,216.497 r0 top
U51 "1N4148X-TP" SOD-523F_L1.2-W0.8-LS1.7-RD 168.95,228.339 r0 top
U52 "FAN48610BUC50X" WLCSP-9_L1.2-W1.2-R3-C3-P0.40-BL 158.184,204.593 r0 top
U53 "470nH" L0806 158.184,198.885 r0 top
U54 "XLMV331IDCKR" SC-70-5_L2.1-W1.3-P0.65-LS2.1-BR 352.852,146.382 r0 top
U55 "1N4148X-TP" SOD-523F_L1.2-W0.8-LS1.7-RD 374.236,130.798 r0 top
U56 "1N4148X-TP" SOD-523F_L1.2-W0.8-LS1.7-RD 360.759,165.932 r0 top
U57 "MM3Z33VT1G" SOD-323_L1.7-W1.3-LS2.5-RD 384.394,124.016 r0 top
U58 "1N4148X-TP" SOD-523F_L1.2-W0.8-LS1.7-RD 366.695,96.577 r0 top
U59 "LMV358AIDGKR" VSSOP-8_L3.0-W3.0-P0.65-LS5.0-BL 433.203,133.338 r0 top
U60 "LMV358AIDGKRG" MSOP-8_L3.0-W3.0-P0.65-LS4.9-BL 407.918,109.139 r0 top
U61 "LMV358AIDGKR" VSSOP-8_L3.0-W3.0-P0.65-LS5.0-BL 431.933,95.272 r0 top
U62 "LMV358AIDGKR" VSSOP-8_L3.0-W3.0-P0.65-LS5.0-BL 321.726,82.575 r0 top
UARTRX "" Test-Point-0.5mm 137.753,291.351 r0 top
USB5V(1) "" Test-Point-0.5mm 226.906,310.042 r0 top
USB5V(2) "" Test-Point-0.5mm 226.906,316.448 r0 top
USBC1 "1054500101" USB-C-SMD_TYPE-C-USB-18 161.086,142.482 r0 top
VIBRO "" Test-Point-0.5mm 175.797,287.701 r0 top
X1 "-" CRYSTAL-SMD_L3.2-W1.5-1 102.908,159.269 r0 top
X2 "32MHz" CRYSTAL-SMD_4P-L3.2-W2.5-BL 137.29,112.711 r0 top
X3 "26MHz" CRYSTAL-SMD_4P-L3.2-W2.5-BL 345.716,179.486 r0 top
X4 "27.12MHz" CRYSTAL-SMD_4P-L2.0-W1.6-BL-B 270.385,216.251 r0 top
XF1 "B0310J50100AHF" XFMR-SMD_6P-L2.1-W1.3-P0.65-BL 392.04,218.076 r0 top

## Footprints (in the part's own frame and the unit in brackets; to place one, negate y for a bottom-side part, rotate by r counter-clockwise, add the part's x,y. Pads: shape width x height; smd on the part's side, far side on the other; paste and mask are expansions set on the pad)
ANT-SMD_L2.0-W1.2-BI [mm]
  rect 0.7x1.3 smd: 1(-0.95,0) 2(0.951,0)
  silkscreen extent -0.37,-0.64 0.37,0.64
BUZ-SMD_4P-L8.5-W8.5-P8.50-BR [mm]
  rect 2.4x2.4 smd: 1(-3.6,-3.6) 2(3.6,-3.6) 3(3.6,3.6) 4(-3.6,3.6)
  silkscreen extent -4.25,-4.25 4.25,4.25
C0201 [mm]
  rect 0.368x0.324 smd paste-100 mask+0.051: 1(-0.274,0) 2(0.274,0)
  silkscreen extent -0.69,-0.39 0.69,0.39
C0402#1 [mm]
  rect 0.5x0.54 smd: 1(-0.42,0) 2(0.42,0)
  silkscreen extent -0.87,-0.5 0.87,0.5
C0402#2 [mm]
  rect 0.5x0.54 smd paste+0 mask+0.051: 1(-0.42,0) 2(0.42,0)
  silkscreen extent -0.87,-0.5 0.87,0.5
C0603 [mm]
  rect 0.8x0.9 smd: 1(-0.7,0) 2(0.7,0)
  silkscreen extent -1.39,-0.71 1.39,0.71
C0805 [mm]
  rect 1.41x1.35 smd paste-100 mask+0.051: 1(-1,0) 2(1,0)
  silkscreen extent -1.96,-0.9 1.96,0.9
C1206 [mm]
  rect 1.485x1.728 smd paste-100 mask+0.051: 1(-1.593,0) 2(1.593,0)
  silkscreen extent -2.56,-1.09 2.56,1.09
CAP-TH_BD13.0-P5.00-D0.6-FD [mm]
  round 1.8 hole 1.1: 1(-2.5,0) 2(2.5,0)
  silkscreen extent -6.5,-6.5 6.5,6.5
COMM-TH_HS12864G18B [mm]
  round 3.8 hole 3: 0(-40.495,-22) 0(-40.495,22) 0(35.585,-22) 0(35.585,22)
  round 1.7 hole 1.1: 1(40.495,-16.51) 2(40.495,-13.97) 3(40.495,-11.43) 4(40.495,-8.89) 5(40.495,-6.35) 6(40.495,-3.81) 7(40.495,-1.27) 8(40.495,1.27) 9(40.495,3.81) 10(40.495,6.35) 11(40.495,8.89) 12(40.495,11.43) 13(40.495,13.97) 14(40.495,16.51)
  round 1.7 hole 1.1 copper offset 0,0: 15(-40.495,-3.81) 16(-40.495,-1.27) 17(-40.495,1.27) 18(-40.495,3.81)
  silkscreen extent -43.5,-25 42.5,25
CONN-SMD_3P-P1.25_SHOU_1.25-3PWTDK [mm]
  rect 0.7x1.5 smd: 1(-1.25,1.75) 2(0,1.75) 3(1.25,1.75)
  rect 1x2.5 smd: 4(-3.05,-1.75) 5(3.05,-1.75)
  silkscreen extent -3.5,-3 3.5,2.08
CONN-SMD_8P-P2.50_SHOUHAN_2.54MM-8PLT [mm]
  rect 1.3x6.5 smd paste+0 mask+0.05: 1(-8.75,1.825) 2(-6.25,1.825) 3(-3.75,1.825) 4(-1.25,1.825) 5(1.25,1.825) 6(3.75,1.825) 7(6.25,1.825) 8(8.75,1.825)
  rect 1.8x3 smd paste+0 mask+0.05: 9(11.65,-1.825) 10(-11.65,-1.825)
  silkscreen extent -12.5,-4.67 12.5,5.44
CONN-SMD_YTC1P-3515-M20 [mm]
  round 2.3 smd paste+0 mask+0.05: 1(0,0)
  silkscreen extent -1.54,-1.54 1.55,1.54
CONN-TH_2P-P2.50_HX-2.54MM-2P-WZ-1 [mm]
  rect 1.9x1.9 hole 1.1 paste+0 mask+0.05: 1(-1.25,0)
  round 1.9 hole 1.1 paste+0 mask+0.05: 2(1.25,0)
  silkscreen extent -3.8,-7.2 3.8,-0.3
CRYSTAL-SMD_4P-L2.0-W1.6-BL-B [mm]
  rect 0.85x0.7 smd: 1(-0.65,-0.45) 2(0.65,-0.45) 3(0.65,0.45) 4(-0.65,0.45)
  silkscreen extent -1.52,-1.4 1.27,1.02
CRYSTAL-SMD_4P-L3.2-W2.5-BL [mm]
  rect 1.4x1.2 smd: 1(-1.1,-0.85) 2(1.1,-0.85) 3(1.1,0.85) 4(-1.1,0.85)
  silkscreen extent -2.26,-1.91 2.03,1.68
CRYSTAL-SMD_L3.2-W1.5-1 [mm]
  rect 1.05x1.7 smd: 1(-1.275,0) 2(1.275,0)
  silkscreen extent -2.03,-1.08 2.03,1.08
DO-41_BD2.4-L4.7-P8.70-D0.9-RD [mm]
  round 1.8 hole 1: 1(-4.35,0) 2(4.35,0)
  silkscreen extent -2.6,-1.4 2.6,1.4
DSBGA-6_L1.4-W1.1-R3-C2-P0.40-BL [mm]
  round 0.216 smd paste-100 mask+0.051: A1(-0.4,-0.2) A2(-0.4,0.2) B1(0,-0.2) B2(0,0.2) C1(0.4,-0.2) C2(0.4,0.2)
  silkscreen extent -1.02,-0.89 0.8,0.68
DSBGA-9_L1.7-W1.6-R3-C3-P0.50-BL [mm]
  round 0.24 smd paste-100 mask+0.038: A1(-0.5,-0.5) A2(-0.5,0) A3(-0.5,0.5) B1(0,-0.5) B2(0,0) B3(0,0.5) C1(0.5,-0.5) C2(0.5,0) C3(0.5,0.5)
  silkscreen extent -0.87,-1.39 0.87,0.89
DSBGA-12_L1.7-W1.3-R3-C4-P0.40-TL [mm]
  round 0.225 smd paste+0 mask+0.05: A1(-0.6,0.4) A2(-0.2,0.4) A3(0.2,0.4) A4(0.6,0.4) B1(-0.6,0) B2(-0.2,0) B3(0.2,0) B4(0.6,0) C1(-0.6,-0.4) C2(-0.2,-0.4) C3(0.2,-0.4) C4(0.6,-0.4)
  silkscreen extent -1.48,-0.73 0.93,0.73
F0402 [mm]
  rect 0.5x0.8 smd: 1(-0.45,0) 2(0.45,0)
  silkscreen extent -0.95,-0.6 0.95,0.6
FFC-SMD_6P-P0.50_FH34SRJ-6S-0.5SH [mm]
  rect 0.3x1 smd: 1(1.25,1.25) 2(0.75,1.25) 3(0.25,1.25) 4(-0.25,1.25) 5(-0.75,1.25) 6(-1.25,1.25)
  rect 0.6x1 smd: 7(-2.25,-1.25) 8(2.25,-1.25)
  silkscreen extent -2.45,-1.63 2.45,2.23
FFC-SMD_18P-P0.50_FH34SRJ-18S-0.5SH [mm]
  rect 0.28x0.9 smd: 1(4.25,1.2) 2(3.75,1.2) 3(3.25,1.2) 4(2.75,1.2) 5(2.25,1.2) 6(1.75,1.2) 7(1.25,1.2) 8(0.75,1.2) 9(0.25,1.2) 10(-0.25,1.2) 11(-0.75,1.2) 12(-1.25,1.2) 13(-1.75,1.2) 14(-2.25,1.2) 15(-2.75,1.2) 16(-3.25,1.2) 17(-3.75,1.2) 18(-4.25,1.2)
  rect 0.5x0.8 smd: 19(-5.2,-1.2) 20(5.2,-1.2)
  silkscreen extent -5.5,-1.65 5.5,2.7
FFC-SMD_30P-P0.50_FH34SRJ-30S-0.5SH [mm]
  rect 0.3x0.8 smd: 1(7.25,1.25) 2(6.75,1.25) 3(6.25,1.25) 4(5.75,1.25) 5(5.25,1.25) 6(4.75,1.25) 7(4.25,1.25) 8(3.75,1.25) 9(3.25,1.25) 10(2.75,1.25) 11(2.25,1.25) 12(1.75,1.25) 13(1.25,1.25) 14(0.75,1.25) 15(0.25,1.25) 16(-0.25,1.25) 17(-0.75,1.25) 18(-1.25,1.25) 19(-1.75,1.25) 20(-2.25,1.25) 21(-2.75,1.25) 22(-3.25,1.25) 23(-3.75,1.25) 24(-4.25,1.25) 25(-4.75,1.25) 26(-5.25,1.25) 27(-5.75,1.25) 28(-6.25,1.25) 29(-6.75,1.25) 30(-7.25,1.25)
  rect 0.4x0.8 smd: 31(-8.25,-1.25) 32(8.25,-1.25)
  silkscreen extent -8.5,-2 8.5,2.05
FILTET-SMD_0603-6P-L1.6-W0.8-P0.50_LFL182G45TC1A108 [mm]
  rect 0.3x0.6 smd: 1(-0.508,0.452) 2(0,0.452) 3(0.508,0.449) 4(0.508,-0.451) 5(0,-0.451) 6(-0.508,-0.451)
  silkscreen extent -1.1,-0.6 1,1.1
FPC-SMD_1.0K-LS-2PWB-TW [mm]
  rect 0.3x1.25 smd: 1(0.5,1.163) 2(-0.5,1.163)
  rect 2x3 smd: 3(-2.5,-1.162) 4(2.5,-1.162)
  silkscreen extent -4.07,-3.96 4.07,1.47
FPC-SMD_6P-P0.50_5051100697 [mm]
  rect 0.3x1 smd: 1(-1.25,1.35) 2(-0.75,1.35) 3(-0.25,1.35) 4(0.25,1.35) 5(0.75,1.35) 6(1.25,1.35)
  rect 2x1.3 smd: 7(-3.485,-1.35) 8(3.485,-1.35)
  silkscreen extent -3.4,-3.75 3.4,1.45
HDR-TH_8P-P2.54-V-M [mm]
  rect 1.5x1.5 hole 1: 1(-8.89,0)
  round 1.5 hole 1: 2(-6.35,0) 3(-3.81,0) 4(-1.27,0) 5(1.27,0) 6(3.81,0) 7(6.35,0) 8(8.89,0)
  silkscreen extent -10.16,-1.27 10.16,1.27
IND-SMD_L1.0-W0.5_LQG15HN1N6B02D [mm]
  rect 0.5x0.54 smd paste+0 mask+0.051: 1(-0.523,0) 2(0.522,0)
  silkscreen extent -1.05,-0.9 1.09,0.5
L0201-RD [mm]
  rect 0.368x0.324 smd paste-100 mask+0.051: 1(-0.274,0) 2(0.274,0)
  silkscreen extent -0.89,-0.39 0.69,0.39
L0402 [mm]
  rect 0.54x0.54 smd: 1(-0.42,0) 2(0.42,0)
  silkscreen extent -1.07,-0.51 1.07,0.49
L0402-RD [mm]
  rect 0.79x0.54 smd paste-100 mask+0.051: 1(-0.545,0) 2(0.545,0)
  silkscreen extent -1.4,-0.57 1.17,0.57
L0805 [mm]
  rect 1.133x1.377 smd paste-100 mask+0.051: 1(-0.966,0) 2(0.966,0)
  silkscreen extent -1.95,-1.02 1.86,1.02
L0806 [mm]
  rect 1.2x1.8 smd: 1(-1,0) 2(1,0)
  silkscreen extent -1.9,-1.2 1.9,1.2
L1008 [mm]
  rect 1.635x2.16 smd paste-100 mask+0.051: 1(-1.168,0) 2(1.168,0)
  silkscreen extent -2.27,-1.27 2.27,1.3
LED-ARRAY-SMD_4P-L1.6-W1.6-TL-CW [mm]
  oval 0.55x0.917 smd: 1(-0.45,0.834) 2(0.45,0.834) 3(0.45,-0.834) 4(-0.45,-0.834)
  Inner2 circle w0.06: c-0.8,-0.8 r0.03
  silkscreen extent -0.88,-0.88 0.88,1.65
LED-SMD_VSMY14940 [mm]
  rect 1.1x1.4 smd: 1(-1.3,0) 2(1.3,0)
  silkscreen extent -1.55,-1.97 1.5,0.97
MSOP-8_L3.0-W3.0-P0.65-LS4.9-BL [mil]
  rect 15.98x55 smd paste+0 mask+2: 1(-38.39,-90.55) 2(-12.8,-90.55) 3(12.8,-90.55) 4(38.39,-90.55) 5(38.39,90.56) 6(12.8,90.56) 7(-12.8,90.55) 8(-38.39,90.55)
  silkscreen extent -59,-86 59,51
QFN-20_L4.0-W4.0-P0.5-TL-EP [mm]
  oval 0.8x0.28 smd: 1(-2,1) 2(-2,0.5) 3(-2,0) 4(-2,-0.5) 5(-2,-1) 11(2,-1) 12(2,-0.5) 13(2,0) 14(2,0.5) 15(2,1)
  oval 0.28x0.8 smd: 6(-1,-2) 7(-0.5,-2) 8(0,-2) 9(0.5,-2) 10(1,-2) 16(1,2) 17(0.5,2) 18(0,2) 19(-0.5,2) 20(-1,2)
  rect 2.4x2.4 smd: 21(0,0)
  silkscreen extent -2.82,-2.15 2.15,2.15
QFN-24_L4.0-W4.0-P0.50-TL-EP2.7 [mm]
  rect 0.633x0.28 smd paste-100 mask+0.051: 1(-1.912,1.25) 2(-1.912,0.75) 3(-1.912,0.25) 4(-1.912,-0.25) 5(-1.912,-0.75) 6(-1.912,-1.25) 13(1.912,-1.25) 14(1.912,-0.75) 15(1.912,-0.25) 16(1.912,0.25) 17(1.912,0.75) 18(1.912,1.25)
  rect 0.28x0.633 smd paste-100 mask+0.051: 7(-1.25,-1.912) 8(-0.75,-1.912) 9(-0.25,-1.912) 10(0.25,-1.912) 11(0.75,-1.912) 12(1.25,-1.912) 19(1.25,1.912) 20(0.75,1.912) 21(0.25,1.912) 22(-0.25,1.912) 23(-0.75,1.912) 24(-1.25,1.912)
  rect 2.7x2.7 smd paste-100 mask+0.051: 25(0,0)
  silkscreen extent -2.42,-2.08 2.08,2.08
QFN-68_L8.0-W8.0-P0.40-TL-EP6.4 [mm]
  rect 0.825x0.2 smd paste-100 mask+0.051: 1(-3.887,3.2) 2(-3.887,2.8) 3(-3.887,2.4) 4(-3.887,2) 5(-3.887,1.6) 6(-3.887,1.2) 7(-3.887,0.8) 8(-3.887,0.4) 9(-3.887,0) 10(-3.887,-0.4) 11(-3.887,-0.8) 12(-3.887,-1.2) 13(-3.887,-1.6) 14(-3.887,-2) 15(-3.887,-2.4) 16(-3.887,-2.8) 17(-3.887,-3.2) 35(3.887,-3.2) 36(3.887,-2.8) 37(3.887,-2.4) 38(3.887,-2) 39(3.887,-1.6) 40(3.887,-1.2) 41(3.887,-0.8) 42(3.887,-0.4) 43(3.887,0) 44(3.887,0.4) 45(3.887,0.8) 46(3.887,1.2) 47(3.887,1.6) 48(3.887,2) 49(3.887,2.4) 50(3.887,2.8) 51(3.887,3.2)
  rect 0.2x0.825 smd paste-100 mask+0.051: 18(-3.2,-3.887) 19(-2.8,-3.887) 20(-2.4,-3.887) 21(-2,-3.887) 22(-1.6,-3.887) 23(-1.2,-3.887) 24(-0.8,-3.887) 25(-0.4,-3.887) 26(0,-3.887) 27(0.4,-3.887) 28(0.8,-3.887) 29(1.2,-3.887) 30(1.6,-3.887) 31(2,-3.887) 32(2.4,-3.887) 33(2.8,-3.887) 34(3.2,-3.887) 52(3.2,3.887) 53(2.8,3.887) 54(2.4,3.887) 55(2,3.887) 56(1.6,3.887) 57(1.2,3.887) 58(0.8,3.887) 59(0.4,3.887) 60(0,3.887) 61(-0.4,3.887) 62(-0.8,3.887) 63(-1.2,3.887) 64(-1.6,3.887) 65(-2,3.887) 66(-2.4,3.887) 67(-2.8,3.887) 68(-3.2,3.887)
  rect 6.4x6.4 smd paste-100 mask+0.051: 69(0,0)
  silkscreen extent -4.5,-4.08 4.08,4.08
R0201 [mm]
  rect 0.303x0.324 smd paste-100 mask+0.051: 1(-0.242,0) 2(0.242,0)
  silkscreen extent -0.62,-0.39 0.62,0.39
R0402 [mm]
  rect 0.566x0.54 smd paste-100 mask+0.051: 1(-0.433,0) 2(0.433,0)
  silkscreen extent -0.94,-0.5 0.94,0.5
R0603 [mm]
  rect 0.806x0.864 smd paste-100 mask+0.051: 1(-0.753,0) 2(0.753,0)
  silkscreen extent -1.39,-0.66 1.39,0.66
R0805 [mm]
  rect 1.133x1.377 smd paste-100 mask+0.051: 1(-1,0) 2(1,0)
  silkscreen extent -1.76,-0.92 1.76,0.92
R1206 [mm]
  rect 1.208x1.701 smd paste-100 mask+0.051: 1(-1.479,0) 2(1.479,0)
  silkscreen extent -2.31,-1.08 2.31,1.08
R2512 [mm]
  rect 1.283x3.456 smd paste-100 mask+0.051: 1(-3.066,0) 2(3.066,0)
  silkscreen extent -3.94,-1.96 3.94,1.96
RES-ARRAY-SMD_0402-8P-L2.0-W1.0-BL [mm]
  rect 0.3x0.505 smd: 1(-0.75,0.427) 2(-0.25,0.427) 3(0.25,0.427) 4(0.75,0.427) 5(0.75,-0.427) 6(0.25,-0.427) 7(-0.25,-0.427) 8(-0.75,-0.427)
  silkscreen extent -1.23,-0.91 1.23,0.91
SC-70-5_L2.1-W1.3-P0.65-LS2.1-BR [mm]
  rect 0.9x0.4 smd: 1(1.1,-0.65) 2(1.1,0) 3(1.1,0.65) 4(-1.1,0.65) 5(-1.1,-0.65)
  silkscreen extent -0.7,-1.4 1.27,1.15
SC-75-3_L1.6-W0.8-P1.00-LS1.7-BR [mm]
  rect 0.585x0.301 smd: 1(0.643,-0.5) 2(0.643,0.5) 3(-0.643,0)
  silkscreen extent -0.38,-0.83 0.38,0.76
SENSOR-SMD_TSOP75238TR [mm]
  rect 0.8x1.8 smd: 1(1.905,0) 2(0.635,0) 3(-0.635,0) 4(-1.905,0)
  silkscreen extent -3.4,-0.64 3.43,2.73
SOD-123_L2.7-W1.6-LS3.7-FD [mm]
  rect 0.88x0.96 smd: 1(-1.61,0) 2(1.61,0)
  silkscreen extent -1.38,-1 1.6,1
SOD-323_L1.7-W1.3-LS2.5-RD [mm]
  rect 0.8x0.8 smd: 1(-1.2,0) 2(1.2,0)
  silkscreen extent -1.1,-0.7 1,0.7
SOD-523F_L1.2-W0.8-LS1.7-RD [mil]
  rect 24x19 smd: 1(-28,0.2) 2(28,-0.2)
  silkscreen extent -29,-19 26,19
SOT-23-3_L2.9-W1.3-P1.90-LS2.4-BR [mm]
  rect 1x0.65 smd: 1(1,-0.95) 2(1,0.95) 3(-1,0)
  silkscreen extent -0.73,-1.53 0.73,1.53
SOT-23-3_L3.0-W1.7-P0.95-LS2.9-BR [mm]
  rect 1.037x0.532 smd: 1(1.101,-0.95) 2(1.101,0.95) 3(-1.101,0)
  silkscreen extent -0.86,-1.53 0.86,1.53
SOT-23-5_L2.9-W1.6-P0.95-LS2.8-BR [mm]
  rect 1x0.6 smd paste+0 mask+0.05: 1(1.1,-0.95) 2(1.1,0) 3(1.1,0.95) 4(-1.1,0.95) 5(-1.1,-0.95)
  silkscreen extent -0.89,-1.52 2.16,1.4
SOT-323-3_L2.2-W1.3-P1.30-LS2.1-BR [mil]
  rect 41.5x32.52 smd: 1(40,-26) 2(40,26) 3(-40,0)
  silkscreen extent -28,-61 44,43
SOT-363_L2.0-W1.3-P0.65-LS2.1-BL [mm]
  rect 0.35x0.78 smd: 1(-0.65,-0.99) 2(0,-0.99) 3(0.65,-0.99) 4(0.65,0.99) 5(0,0.99) 6(-0.65,0.99)
  silkscreen extent -1.43,-1.14 1.08,0.7
SOT-523-3_L1.6-W0.8-P1.00-LS1.6-BR [mm]
  rect 0.51x0.4 smd: 1(0.65,-0.5) 2(0.65,0.5) 3(-0.65,0)
  silkscreen extent -0.45,-1.08 0.83,0.9
SW-SMD_4P-L4.5-W4.5-P3.30-S3.75 [mm]
  rect 1.2x0.7 smd: 1(-1.85,1.65) 2(1.85,1.65) 3(-1.85,-1.65) 4(1.85,-1.65)
  silkscreen extent -2.25,-2.25 2.25,2.25
Test-Point-0.5mm [mm]
  round 0.5 smd: 1(0,0)
TF-SMD_503398-1892 [mm]
  rect 0.7x1.1 smd: 1(-2.42,6.27) 2(-1.32,6.27) 3(-0.22,6.27) 4(0.88,6.27) 5(1.98,6.27) 6(3.08,6.27) 7(4.18,6.27) 8(5.28,6.27)
  rect 1.05x0.78 smd: 9(0.095,-6.27)
  rect 0.9x0.9 smd: 10(-4.17,-6.21)
  rect 0.7x3.33 smd: 11(-6.48,-4.995) 11(6.48,-4.995)
  rect 1.14x1.83 smd: 11(-6.26,6.255)
  rect 0.86x2.8 smd: 11(6.4,5.77)
  silkscreen extent -6.55,-6.27 6.55,7.78
TSNP-9_L1.1-W1.1-P0.40-BL [mm]
  rect 0.2x0.2 smd: 1(-0.4,-0.4) 2(0,-0.4) 3(0.4,-0.4) 4(0.4,0) 5(0.4,0.4) 6(0,0.4) 7(-0.4,0.4) 8(-0.4,0) 9(0,0)
  silkscreen extent -0.9,-0.9 0.68,0.68
USB-C-SMD_TYPE-C-USB-18 [mm]
  oval 1x2.6 hole 0.6 slot 2.1 at 90 deg paste+0 mask+0.05: 0(-4.32,-2.91) 0(4.32,-2.91)
  oval 1x2.1 hole 0.6 slot 1.6 at 90 deg paste+0 mask+0.05: 0(-4.32,2.45) 0(4.32,2.45)
  rect 0.3x0.8 smd paste-100 mask+0.051: A1(-3,2.91) A2(-2.5,2.91) A3(-2,2.91) A4(-1.5,2.91) A5(-1,2.91) A6(-0.5,2.91) A7(0.5,2.91) A8(1,2.91) A9(1.5,2.91) A10(2,2.91) A11(2.5,2.91) A12(3,2.91)
  rect 1x0.7 smd paste-100 mask+0.05: B1(3.1,1.56) B12(-3.1,1.56)
  rect 0.3x0.7 smd paste-100 mask+0.051: B2(2.25,1.56) B3(1.75,1.56) B4(1.25,1.56) B5(0.75,1.56) B6(0.25,1.56) B7(-0.25,1.56) B8(-0.75,1.56) B9(-1.25,1.56) B10(-1.75,1.56) B11(-2.25,1.56)
  silkscreen extent -4.32,-4.68 4.32,3.66
VFQFPN-32_L5.0-W5.0-P0.50-TL-EP3.5 [mm]
  rect 0.665x0.28 smd paste-100 mask+0.051: 1(-2.42,1.75) 2(-2.42,1.25) 3(-2.42,0.75) 4(-2.42,0.25) 5(-2.42,-0.25) 6(-2.42,-0.75) 7(-2.42,-1.25) 8(-2.42,-1.75) 17(2.42,-1.75) 18(2.42,-1.25) 19(2.42,-0.75) 20(2.42,-0.25) 21(2.42,0.25) 22(2.42,0.75) 23(2.42,1.25) 24(2.42,1.75)
  rect 0.28x0.665 smd paste-100 mask+0.051: 9(-1.75,-2.42) 10(-1.25,-2.42) 11(-0.75,-2.42) 12(-0.25,-2.42) 13(0.25,-2.42) 14(0.75,-2.42) 15(1.25,-2.42) 16(1.75,-2.42) 25(1.75,2.42) 26(1.25,2.42) 27(0.75,2.42) 28(0.25,2.42) 29(-0.25,2.42) 30(-0.75,2.42) 31(-1.25,2.42) 32(-1.75,2.42)
  rect 3.5x3.5 smd paste-100 mask+0.051: 33(0,0)
  silkscreen extent -2.9,-2.5 2.5,2.5
VSSOP-8_L3.0-W3.0-P0.65-LS5.0-BL [mm]
  oval 0.364x1.662 smd: 1(-0.975,-2.131) 2(-0.325,-2.131) 3(0.325,-2.131) 4(0.975,-2.131) 5(0.975,2.131) 6(0.325,2.131) 7(-0.325,2.131) 8(-0.975,2.131)
  silkscreen extent -1.76,-2.28 1.58,1.07
WLCSP-9_L1.2-W1.2-R3-C3-P0.40-BL [mm]
  round 0.208 smd: A1(-0.4,-0.4) A2(-0.4,0) A3(-0.4,0.4) B1(0,-0.4) B2(0,0) B3(0,0.4) C1(0.4,-0.4) C2(0.4,0) C3(0.4,0.4)
  silkscreen extent -0.7,-1.02 0.7,0.7
WLL-2-1_L0.6-W0.3-BI [mm]
  rect 0.24x0.32 smd: 1(-0.203,0) 2(0.203,0)
  silkscreen extent -0.5,-0.33 0.5,0.33
WLL-2-3_L0.6-W0.3-P0.36-BI [mm]
  rect 0.2x0.3 smd: 1(-0.2,0) 2(0.2,0)
  silkscreen extent -0.5,-0.33 0.5,0.33
XFMR-SMD_6P-L2.1-W1.3-P0.65-BL [mm]
  rect 0.41x0.33 smd: 1(-0.65,-0.495) 2(0,-0.495) 3(0.65,-0.495) 4(0.65,0.495) 5(0,0.495) 6(-0.65,0.495)
  silkscreen extent -1.4,-0.8 1.05,0.8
